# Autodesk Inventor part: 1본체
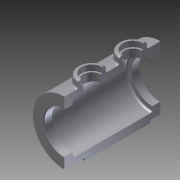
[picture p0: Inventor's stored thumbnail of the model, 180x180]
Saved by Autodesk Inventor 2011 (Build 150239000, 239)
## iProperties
Created: 2014-12
Part Number: 1본체
Document SubType Name: Modeling
Designer: user
Density: 1 g/cm^3
Mass: 477.257 g
Surface Area: 1040.04 cm^2
Volume: 477.257 cm^3
Author: user
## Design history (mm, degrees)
sketch "스케치1"
  geometry: L1 (0, 0)-(130, 0); L2 (130, 0)-(130, 95); L3 (130, 95)-(0, 95); L4 (0, 95)-(0, 0)
  constraints: 8 end point, 2 parallel, 1 horizontal, 1 perpendicular
  dimensions: "d0" = 130 distance of L3.end L2.end; "d1" = 95 distance of L2.end L1.end
extrude "돌출1" new body sketch "스케치1" distance "d2" = 12; taper "d3" = 0 deg
sketch "스케치2"
  geometry: L1 (0, 0)-(0, 12) reference; L2 (0, 0)-(130, 0) reference; L3 (130, 12)-(130, 0) reference; L4 (130, 0)-(0, 0) reference; L5 (0, 0)-(0, 12) reference; L6 (0, 12)-(130, 12) reference; C1 r 46 at (65, 50)
  constraints: 1 centre point
  dimensions: "d4" = 92 diameter of C1; "d5" = 50 distance from line of L2 C1.centre; "d6" = 65 distance from line of L1 C1.centre
extrude "돌출2" join sketch "스케치2" distance "d7" = 30; taper "d9" = 0 deg; dims "d8" = 110, "d10" = 0
node "작업 평면1"
sketch "스케치3"
  geometry: L1 (-96, -30)-(-96, 110) reference; L2 (-96, 110)-(-4, 110) reference; L3 (-4, 110)-(-4, 95) reference; L4 (-4, 95)-(0, 95) reference; L5 (0, 95)-(0, 0) reference; L6 (0, 0)-(-4, 0) reference; L7 (-4, 0)-(-4, -30) reference; L8 (-4, -30)-(-96, -30) reference; L9 (-106, -10)-(-58.648, -10); L10 (-58.648, -10)-(-58.648, 10); L11 (-58.648, 10)-(-106, 10); L12 (-106, 10)-(-106, -10)
  constraints: 8 end point, 2 parallel, 1 horizontal, 1 perpendicular
  dimensions: "d11" = 40 distance between parallel lines of L8 L11; "d12" = 20 distance of L11.end L9.start; "d13" = 106 distance between parallel lines of L5 L12
revolve "회전1" sketch "스케치3" stored, may be unused: angle "d14" = 90 deg
sketch "스케치4"
  geometry: L1 (-4, 0)-(-4, -30) reference; L2 (-4, -30)-(-96, -30) reference; L3 (-96, -30)-(-96, -10) reference; L4 (-96, -10)-(-106, -10) reference; L5 (-106, -10)-(-106, 30) reference; L6 (-106, 30)-(-96, 30) reference; L7 (-96, 30)-(-96, 110) reference; L8 (-96, 110)-(-4, 110) reference; L9 (-4, 110)-(-4, 95) reference; L10 (-4, 95)-(0, 95) reference; L11 (0, 95)-(0, 0) reference; L12 (0, 0)-(-4, 0) reference; L13 (-106, 70)-(-64.183, 70); L14 (-64.183, 70)-(-64.183, 90); L15 (-64.183, 90)-(-106, 90); L16 (-106, 90)-(-106, 70)
  constraints: 8 end point, 2 parallel, 1 horizontal, 1 perpendicular
  dimensions: "d15" = 40 distance between parallel lines of L8 L13; "d16" = 20 distance of L15.end L13.start; "d17" = 106 distance between parallel lines of L11 L16
revolve "회전2" sketch "스케치4" stored, may be unused: angle "d18" = 90 deg
node "작업 평면2"
sketch "스케치5"
  geometry: L1 (-111, -30)-(-111, 110) reference; L2 (-111, 110)-(-19, 110) reference; L3 (-19, 110)-(-19, -30) reference; L4 (-19, -30)-(-111, -30) reference; L5 (-95, -42.03)-(-65, -42.03); L6 (-65, -42.03)-(-65, 144.703); L7 (-65, 144.703)-(-95, 144.703); L8 (-102.5, -18)-(-95, -18); L9 (-65, -18)-(-65, 98); L10 (-95, 98)-(-102.5, 98); L11 (-102.5, 98)-(-102.5, -18); L12 (-95, 144.703)-(-95, 98); L13 (-95, -18)-(-95, -42.03); 1 further point
  constraints: 18 end point, 5 parallel, 2 horizontal, 2 perpendicular, 1 point on line
  dimensions: "d20" = 46 distance between parallel lines of L1 L6; "d21" = 92 distance between parallel lines of L3 L1 (derived); "d23" = 37.5 distance between parallel lines of L6 L11; "d24" = 12 distance between parallel lines of L2 L10; "d25" = 12 distance between parallel lines of L4 L8
revolve "회전3" sketch "스케치5" stored, may be unused: angle "d26" = 90 deg
sketch "스케치6"
  geometry: C1 r 20 at (0, 0) reference; C2 r 20 at (0, -60) reference; 3 further points
  constraints: 2 coincident
hole "Hole1" sketch "스케치6" at (0, 0), (0, -60) diameter "d27" = 25; stored, may be unused: countersink angle "d31" = 90 deg, drill point angle "d33" = 118 deg; dims "d28" = 6, "d29" = 30, "d30" = 8, "d32" = 30
sketch "스케치7"
  geometry: L1 (0, 0)-(-53.702, 53.702); L2 (0, 0)-(75.945, 0); L3 (0, 0)-(0, 40); C1 r 46 at (0, 0) reference; C2 r 30 at (0, 0) reference; A1 r 40 centre (0, 0) between (-28.284, 28.284) and (0, 40); 1 further point
  constraints: 6 end point, 2 coincident, 2 point on circle, 1 centre point, 1 equal length, 1 horizontal, 1 point on line
  dimensions: "d34" = 135 deg angle of L2 L1; "d35" = 80 diameter of A1
hole "Hole2" sketch "스케치7" at (-28.284, 28.284) diameter "d36" = 3.242; stored, may be unused: countersink angle "d40" = 90 deg, drill point angle "d42" = 118 deg; dims "d37" = 8, "d38" = 30, "d39" = 8, "d41" = 10
node "작업 평면3"
fillet "모깎기1" dims "d46" = 10
sketch "스케치8"
  geometry: L1 (90.923, 110)-(90.923, 95) reference; L2 (90.923, 95)-(90.923, 0) reference; L3 (120, 0)-(90.923, 0) reference; L4 (130, 85)-(130, 10) reference; L5 (90.923, 95)-(120, 95) reference; L6 (39.077, 110)-(90.923, 110) reference; L7 (39.077, 95)-(39.077, 110) reference; L8 (10, 95)-(39.077, 95) reference; L9 (0, 10)-(0, 85) reference; L10 (39.077, 0)-(10, 0) reference; L11 (39.077, -30)-(39.077, 0) reference; L12 (90.923, -30)-(39.077, -30) reference; L13 (90.923, 0)-(90.923, -30) reference; L14 (39.077, 0)-(39.077, 95) reference; L15 (65, 120.179)-(65, -80.262); A1 r 10 centre (120, 10) between (120, 0) and (130, 10) reference; A2 r 10 centre (120, 85) between (130, 85) and (120, 95) reference; A3 r 10 centre (10, 85) between (10, 95) and (0, 85) reference; A4 r 10 centre (10, 10) between (0, 10) and (10, 0) reference; 5 further points
  constraints: 2 end point, 1 parallel
  dimensions: "d47" = 104 distance of point (13, 82.5) point (117, 82.5); "d48" = 25.92296 distance between parallel lines of L13 L15; "d49" = 65 distance between parallel lines of L15 L4 (derived); "d50" = 52 distance from line of L15 point (117, 82.5); "d51" = 12.5 distance from line of L5 point (117, 82.5); "d52" = 12.5 distance from line of L3 point (117, 12.5)
hole "Hole3" sketch "스케치8" at (13, 82.5), (117, 82.5), (117, 12.5), (13, 12.5) diameter "d53" = 11; stored, may be unused: countersink angle "d57" = 90 deg, drill point angle "d59" = 118 deg; dims "d54" = 8, "d55" = 30, "d56" = 8, "d58" = 30
fillet "모깎기2" dims "d60" = 3
fillet "모깎기3" dims "d61" = 3
fillet "모깎기4" dims "d62" = 5
fillet "모깎기5" dims "d63" = 3
sketch "스케치9"
  geometry: L1 (103.884, 0)-(120, 0) reference; L2 (120, 95)-(103.884, 95) reference; L3 (130, 10)-(130, 85) reference; C1 r 5.5 at (117, 12.5) reference; 2 further points
  constraints: 1 other
  dimensions: "d64" = 35 vertical distance of C1.centre point (122, 47.5); "d65" = 8 distance from line of L3 point (122, 47.5)
feature "엠보싱1" sketch "스케치9" dims "d0" = 130, "d1" = 95, "d66" = 1, "d67" = 0
chamfer "모따기1" distance "d68" = 1; stored, may be unused: second distance "d69" = 2, angle "d70" = 45 deg
node "작업 평면4"
sketch "스케치10"
  geometry: L1 (-159.082, 115.175)-(68.394, 115.175); L2 (68.394, 115.175)-(68.394, -82.37); L3 (68.394, -82.37)-(-159.082, -82.37); L4 (-159.082, -82.37)-(-159.082, 115.175); 1 further point
  constraints: 8 end point, 2 parallel, 1 horizontal, 1 perpendicular
extrude "돌출3" cut sketch "스케치10" distance "d71" = 300; taper "d72" = 0 deg
node "솔리드1"
pattern_circular "원형 패턴1" dims angle "d44" = 360 deg
mirror "대칭1"
node "절단 모서리 투영1"
node "절단 모서리 투영2"
node "절단 모서리 투영3"
node "절단 모서리 투영4"
node "절단 모서리 투영5"
node "절단 모서리 투영6"
